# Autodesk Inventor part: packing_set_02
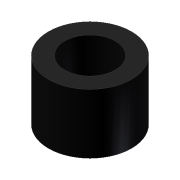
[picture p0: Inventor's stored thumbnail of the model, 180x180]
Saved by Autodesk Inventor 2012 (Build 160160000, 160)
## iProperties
Shininess: 64.0
Length Units: 11269
Angle Units: 11279
Time Units: 11290
Mass Units: 11283
Length Display Precision: 3
Angle Display Precision: 2
Company: Autodesk
Created: 2002-07
Part Number: packing_set_02
Document SubType Name: Modeling
Designer: Lieven Grauls
Stock Number: packing_set_02
Project: Valve Techcamp 2008
Density: 1 g/cm^3
Mass: 3.22623 g
Surface Area: 20.2371 cm^2
Volume: 3.22623 cm^3
Material: Default
Density: 0.0
Volumn: 0.0
Area: 0.0
PropertySet Name: Model Information
Control State: 0
Master: False
Checked Out: False
Author: Lieven Grauls
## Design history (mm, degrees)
sketch "Sketch1"
  geometry: C1 r 6.75 at (0, 0); C2 r 11.12 at (0, 0); 1 further point
  constraints: 2 centre point, 1 coincident, 1 concentric
extrude "Extrusion1" new body sketch "Sketch1" distance "d0" = 16; taper "d1" = 0 deg
sketch "Sketch2"
  geometry: L1 (-15.81, 0)-(17.023, 0) reference; L2 (0, -17.023)-(0, 15.81) reference; L3 (2, -2)-(10.939, -2); L4 (2, -2)-(2, -10.939); A1 r 11.12 centre (0, 0) between (10.939, -2) and (2, -10.939) reference; A2 r 11.12 centre (0, 0) between (2, -10.939) and (10.939, -2); 1 further point
  constraints: 4 end point, 4 point on circle, 2 perpendicular, 1 centre point, 1 coincident
  dimensions: "d6" = 2 distance between parallel lines of L4 L2; "d7" = 2 distance between parallel lines of L3 L1
extrude "Extrusion2" cut sketch "Sketch2" stored distance "d4" = 10; taper "d5" = 0 deg
node "Volumenkörper1"
node "Volumenkörpern"
node "Oberflächenkörpern"
